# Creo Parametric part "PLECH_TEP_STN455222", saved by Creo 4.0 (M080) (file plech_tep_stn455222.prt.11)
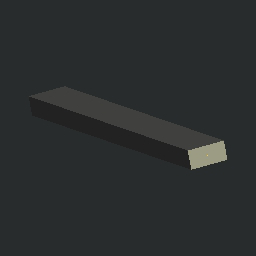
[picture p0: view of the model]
Units: Custom; MM, KILOGRAM, SECS
Materials in the file: OCEL_N

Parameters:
  NORMINFO = "Stabstahl Formstahl; Warmgewalzter rundkantiger U-Stahl"
  FESTIGKEIT = "."
  N_D = "0"
  B_D = "5"
  KATEGORIE = "0"
  DESIGNER = "."
  DATE = "."
  FORMAT = "."
  MOD_INDEX_1 = "."
  MOD_INDEX_2 = "."
  MOD_INDEX_3 = "."
  MOD_INDEX_4 = "."
  MOD_INDEX_5 = "."
  MOD_INDEX_6 = "."
  MOD_INDEX_7 = "."
  MOD_INDEX_8 = "."
  MOD_NOTE_1 = "."
  MOD_NOTE_2 = "."
  MOD_NOTE_3 = "."
  MOD_NOTE_4 = "."
  MOD_NOTE_5 = "."
  MOD_NOTE_6 = "."
  MOD_NOTE_7 = "."
  MOD_NOTE_8 = "."
  MOD_DATE_1 = "."
  MOD_DATE_2 = "."
  MOD_DATE_3 = "."
  MOD_DATE_4 = "."
  MOD_DATE_5 = "."
  MOD_DATE_6 = "."
  MOD_DATE_7 = "."
  MOD_DATE_8 = "."
  MOD_NAME_1 = "."
  MOD_NAME_2 = "."
  MOD_NAME_3 = "."
  MOD_NAME_4 = "."
  MOD_NAME_5 = "."
  MOD_NAME_6 = "."
  MOD_NAME_7 = "."
  MOD_NAME_8 = "."
  NAZOV = "PLECH_TEP_STN455222"
  ROZMER = "PL 10x5x100"
  NORMA = "STN 45 5222"
  HMOTNOST_HR = "."
  MATERIAL_ZAKL = "."
  PTC_MATERIAL_NAME = "OCEL_N"

Other parameters: L, T, QUERSCHNITT, B, HMOTNOST, HUSTOTA, HMOTNOST_1, D23, D1

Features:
  1. datum plane "Y-Y"
  2. datum plane "X-X"
  3. datum plane "Z-Z"
  4. coordinate system
  5. datum axis
  6. datum axis
  7. datum axis
  8. protrusion
  9. datum point "PNT0"
  10. datum point "PNT1"
  11. curve

Other named items: ZZ, XX, YY, CS0

Named dimensions: dicke, Laenge, laenge_nf, breite

Layers: BEZUG, BEZUGSACHSEN, KONSTRUKTIONSELEMENTE, PLAZIERUNG, PROFIL_NEUTRALE_FASER

Notes: Flachstahl | FL 10x5x100 DIN 1017 | Gewicht:  | 0.087 | Querschnittsfläche: A=  | 0.500 |  cm²

Family table entries: GENERIC, PLECH_12X5, PLECH_TEP_STN455222, value(d_val), value(i_val), PLECH_12X6, PLECH_TEP_STN455222, !/(, PLECH_14X5, PLECH_TEP_STN455222, !/,, PLECH_14X6, PLECH_TEP_STN455222, !/,, PLECH_14X7, PLECH_TEP_STN455222, !/,, PLECH_14X8, PLECH_TEP_STN455222, !/,, 2/ , PLECH_15X5, PLECH_TEP_STN455222, !/., PLECH_15X6, PLECH_TEP_STN455222, !/., PLECH_15X7, PLECH_TEP_STN455222, !/., PLECH_15X8, PLECH_TEP_STN455222, !/., 2/ , PLECH_15X10, PLECH_TEP_STN455222, !/., 2/$, PLECH_16X5, PLECH_TEP_STN455222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

Surfaces: 6 plane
